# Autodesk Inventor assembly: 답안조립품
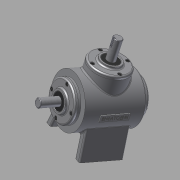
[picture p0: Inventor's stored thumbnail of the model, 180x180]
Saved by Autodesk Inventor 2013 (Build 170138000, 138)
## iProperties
Created: 2015-01
Part Number: 답안조립품
Document SubType Name: Assembly
Designer: Administrator
Author: Administrator
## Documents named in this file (15)
- C:\Users\Administrator\Desktop\450106V1032\답안조립품.iam
- C:\Users\Administrator\Desktop\450106V1032\본체.ipt
- C:\Users\Administrator\Desktop\450106V1032\서브 축.ipt
- 서브 축.ipt
- C:\Users\Administrator\Desktop\450106V1032\서브 베벨기어.ipt
- C:\Users\Administrator\Desktop\450106V1032\키 4x4.ipt
- C:\Users\Administrator\Desktop\450106V1032\커버.ipt
- C:\Users\Administrator\Desktop\450106V1032\베어링 6203.ipt
- C:\Users\Administrator\Desktop\450106V1032\오일실.ipt
- C:\Users\Administrator\Desktop\450106V1032\M4.ipt
- C:\Users\Administrator\Desktop\450106V1032\메인 축.ipt
- 메인 축.ipt
- C:\Users\Administrator\Desktop\450106V1032\키 5x5.ipt
- C:\Users\Administrator\Desktop\450106V1032\메인 베벨기어.ipt
- C:\Users\Administrator\Desktop\450106V1032\커버2.ipt
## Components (12 placed, 1 different names)
1. M4:1
2. M4:2
3. M4:3
4. M4:4
5. M4:5
6. M4:6
7. M4:7
8. M4:8
9. M4:9
10. M4:10
11. M4:11
12. M4:12
